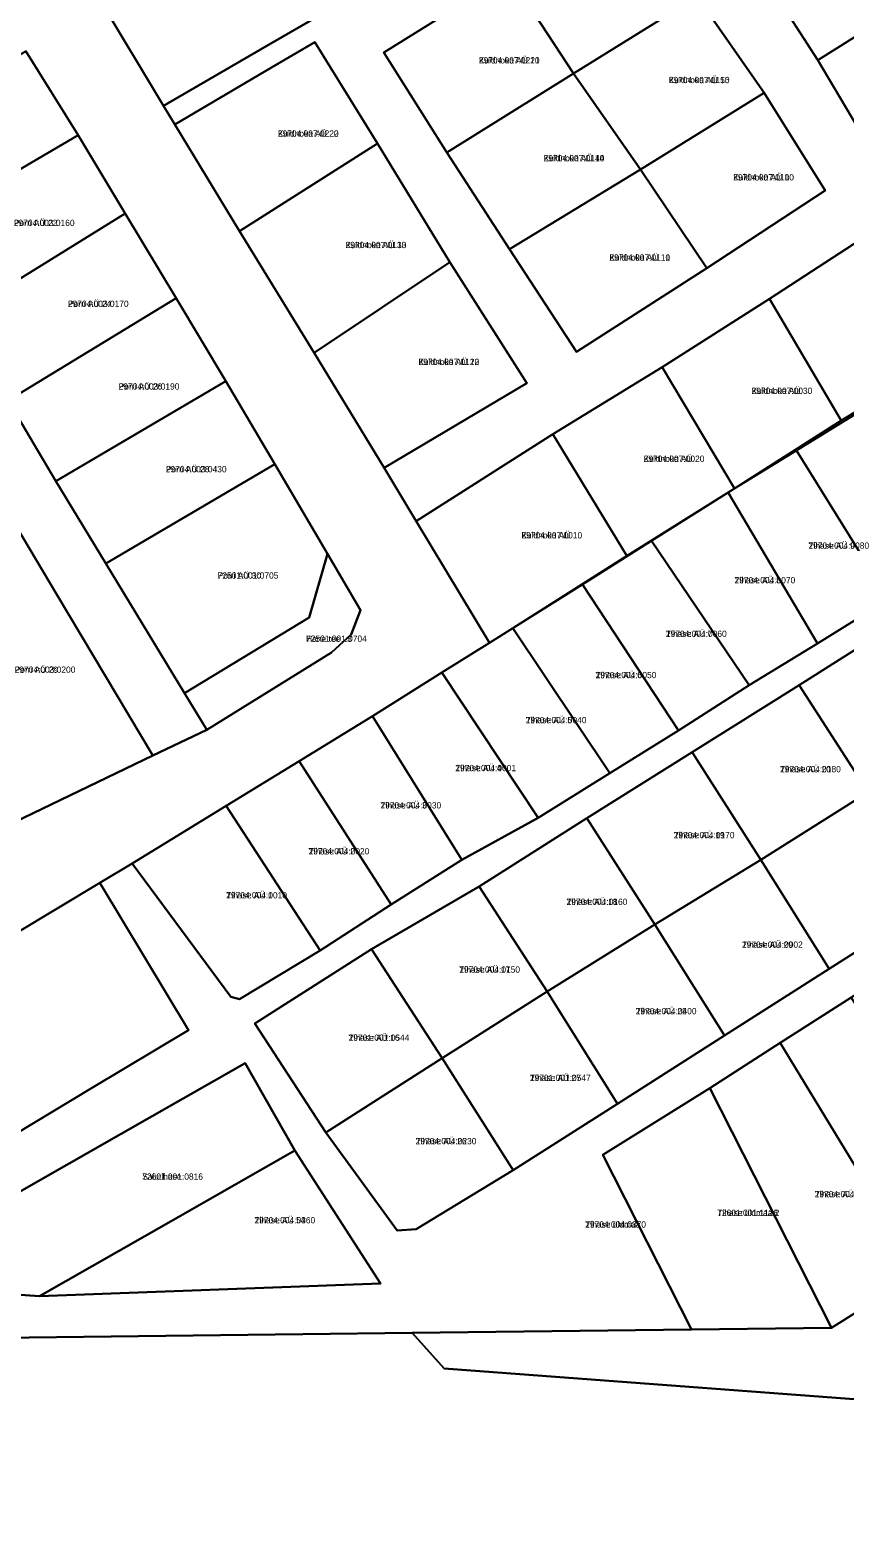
# Model space of a CAD drawing. Extents: x 504287 to 537970, y 6539941 to 6586214.
# Drawn here: x 516534.2 to 516728.7, y 6563396.7 to 6563756.4 of the extents above; entities that cross this region are included whole.
import ezdxf

# ---------------------------------------------------------------- set-up
doc = ezdxf.new("R2010")
doc.units = 0
for name, color, linetype in [('L_AADRESS', 7, 'Continuous'), ('PIIR', 7, 'Continuous'), ('TUNNUS', 7, 'Continuous')]:
    doc.layers.add(name, color=color, linetype=linetype)

msp = doc.modelspace()

# ---------------------------------------------------------------- linework, layer by layer
at = {"layer": 'PIIR'}
for points in [[(516722.29, 6563749.26), (516735.69, 6563726.63), (516766.07, 6563743.18), (516799.74, 6563764.29), (516785.62, 6563789.05), (516771.4, 6563813.09), (516757.06, 6563837.14), (516721.19, 6563815.1), (516692.06, 6563796.82), (516706.99, 6563772.95)], [(516623.67, 6563811.4), (516643.03, 6563783.07), (516624.17, 6563770.73), (516623.2, 6563772.02), (516617.83, 6563768.33), (516591.67, 6563753.24), (516566.1, 6563738.35), (516550.62, 6563764.18), (516575.1, 6563780.13), (516585.67, 6563787.07), (516593.53, 6563792.11), (516615.66, 6563806.42)], [(516706.99, 6563772.95), (516736.13, 6563791.14), (516751.12, 6563767.4), (516722.29, 6563749.26)], [(516648.67, 6563704.2), (516664.67, 6563679.71), (516695.76, 6563699.65), (516724.03, 6563718.14), (516709.44, 6563741.49), (516693.5, 6563764.43), (516679.56, 6563788.61), (516648.53, 6563769.72), (516618.65, 6563751.1), (516633.73, 6563727.26)], [(516648.53, 6563769.72), (516679.56, 6563788.61), (516693.5, 6563764.43), (516663.97, 6563746.07)], [(516618.65, 6563751.1), (516648.53, 6563769.72), (516663.97, 6563746.07), (516633.73, 6563727.26)], [(516663.97, 6563746.07), (516693.5, 6563764.43), (516709.44, 6563741.49), (516679.91, 6563723.16)], [(516722.29, 6563749.26), (516751.12, 6563767.4), (516766.07, 6563743.18), (516735.69, 6563726.63)], [(516568.78, 6563733.94), (516591.84, 6563747.49), (516602.18, 6563753.59), (516617.19, 6563729.39), (516584.22, 6563708.44)], [(516493.11, 6563727.7), (516533.21, 6563751.45), (516545.71, 6563731.34), (516505.34, 6563707.79)], [(516633.73, 6563727.26), (516663.97, 6563746.07), (516679.91, 6563723.16), (516648.67, 6563704.2)], [(516709.44, 6563741.49), (516724.03, 6563718.14), (516695.76, 6563699.65), (516679.91, 6563723.16)], [(516505.34, 6563707.79), (516545.71, 6563731.34), (516556.93, 6563712.69), (516517.08, 6563688.04)], [(516584.22, 6563708.44), (516617.19, 6563729.39), (516634.4, 6563701.07), (516602.05, 6563679.44)], [(516695.76, 6563699.65), (516664.67, 6563679.71), (516648.67, 6563704.2), (516679.91, 6563723.16)], [(516517.08, 6563688.04), (516556.93, 6563712.69), (516569.06, 6563692.51), (516528.99, 6563668.1)], [(516710.76, 6563692.3), (516732.39, 6563706.39), (516736.08, 6563707.1), (516752.91, 6563678.97), (516751.32, 6563677.47), (516727.82, 6563663.32)], [(516634.4, 6563701.07), (516652.8, 6563672.2), (516618.72, 6563651.98), (516602.05, 6563679.44)], [(516528.99, 6563668.1), (516569.06, 6563692.51), (516580.96, 6563672.68), (516540.37, 6563648.81)], [(516685.1, 6563676.01), (516710.76, 6563692.3), (516727.82, 6563663.32), (516702.36, 6563647.05)], [(516659.05, 6563660.05), (516685.1, 6563676.01), (516702.36, 6563647.05), (516676.66, 6563631)], [(516580.96, 6563672.68), (516592.61, 6563652.86), (516552.31, 6563629.16), (516540.37, 6563648.81)], [(516733.94, 6563666.48), (516756.7, 6563631.52), (516739.21, 6563620.66), (516717.18, 6563656.16)], [(516626.42, 6563639.26), (516659.05, 6563660.05), (516676.66, 6563631), (516649.46, 6563613.73), (516643.89, 6563610.25)], [(516702.36, 6563647.05), (516717.18, 6563656.16), (516739.21, 6563620.66), (516722.21, 6563610.11), (516700.84, 6563646.09)], [(516600.85, 6563616.31), (516571.09, 6563598.26), (516552.31, 6563629.16), (516592.61, 6563652.86), (516605.19, 6563631.46)], [(516700.84, 6563646.09), (516722.21, 6563610.11), (516705.92, 6563600.17), (516682.56, 6563634.57)], [(516497.49, 6563622.01), (516529.15, 6563640.98), (516540.67, 6563621.62), (516563.56, 6563583.34), (516530.47, 6563567.46), (516508.46, 6563602.44)], [(516682.56, 6563634.57), (516705.92, 6563600.17), (516688.99, 6563589.3), (516666.12, 6563624.14)], [(516605.19, 6563631.46), (516613.07, 6563618.05), (516610.84, 6563612.22), (516606.19, 6563607.91), (516576.41, 6563589.5), (516571.09, 6563598.26), (516600.85, 6563616.31)], [(516666.12, 6563624.14), (516688.99, 6563589.3), (516672.59, 6563579.17), (516649.46, 6563613.73)], [(516649.46, 6563613.73), (516672.59, 6563579.17), (516655.53, 6563568.5), (516632.5, 6563603.12), (516643.89, 6563610.25)], [(516743.18, 6563616.21), (516759.74, 6563590.32), (516759.36, 6563589.97), (516734.29, 6563574.56), (516717.81, 6563600.13)], [(516725.56, 6563446.76), (516746.61, 6563460.01), (516763.92, 6563471.26), (516781.08, 6563482.33), (516797.71, 6563493.29), (516814.71, 6563504.25), (516831.42, 6563515.11), (516848.12, 6563525.98), (516865.33, 6563536.97), (516882.68, 6563548.06), (516898.91, 6563558.38), (516921.33, 6563573.01), (516927.25, 6563577.2), (516982.09, 6563611.59), (517112.27, 6563384.86), (517064.02, 6563325.01), (516892.69, 6563483.77), (516884.06, 6563418.3), (516633.11, 6563437.06), (516625.46, 6563445.55), (516692.12, 6563446.36)], [(516632.5, 6563603.12), (516655.53, 6563568.5), (516637.29, 6563558.49), (516615.95, 6563592.72)], [(516692.25, 6563584.15), (516717.81, 6563600.13), (516734.29, 6563574.56), (516708.64, 6563558.48)], [(516615.95, 6563592.72), (516637.29, 6563558.49), (516620.44, 6563547.76), (516598.44, 6563581.96)], [(516598.44, 6563581.96), (516620.44, 6563547.76), (516603.46, 6563536.85), (516580.99, 6563571.31)], [(516667.15, 6563568.39), (516692.25, 6563584.15), (516708.64, 6563558.48), (516683.34, 6563543)], [(516734.29, 6563574.56), (516750.56, 6563548.68), (516725.02, 6563532.42), (516708.64, 6563558.48)], [(516580.99, 6563571.31), (516603.46, 6563536.85), (516584.18, 6563525.23), (516582.15, 6563525.76), (516558.61, 6563557.61)], [(516641.42, 6563552.09), (516667.15, 6563568.39), (516683.34, 6563543), (516657.65, 6563527.01)], [(516708.64, 6563558.48), (516725.02, 6563532.42), (516699.99, 6563516.5), (516683.34, 6563543)], [(516458.32, 6563497.36), (516550.89, 6563552.98), (516572.01, 6563517.83), (516548.86, 6563503.93), (516525.72, 6563490.03), (516502.57, 6563476.12), (516479.43, 6563462.22)], [(516641.42, 6563552.09), (516657.65, 6563527.01), (516632.63, 6563511.14), (516615.72, 6563537.12)], [(516683.34, 6563543), (516699.99, 6563516.5), (516674.46, 6563500.24), (516657.65, 6563527.01)], [(516615.72, 6563537.12), (516632.63, 6563511.14), (516604.84, 6563493.42), (516587.89, 6563519.38)], [(516657.65, 6563527.01), (516674.46, 6563500.24), (516649.55, 6563484.39), (516632.63, 6563511.14)], [(516730.23, 6563525.6), (516763.92, 6563471.26), (516746.61, 6563460.01), (516713.3, 6563514.8)], [(516713.3, 6563514.8), (516746.61, 6563460.01), (516725.56, 6563446.76), (516696.5, 6563504)], [(516617.86, 6563457.38), (516597.41, 6563489.08), (516585.53, 6563509.93), (516555.99, 6563493.09), (516493.29, 6563457.33), (516536.45, 6563454.32)], [(516493.29, 6563457.33), (516555.99, 6563493.09), (516585.53, 6563509.93), (516597.41, 6563489.08), (516567.88, 6563472.24), (516536.45, 6563454.32)], [(516649.55, 6563484.39), (516626.42, 6563470.34), (516621.82, 6563470.01), (516604.84, 6563493.42), (516632.63, 6563511.14)], [(516692.12, 6563446.36), (516670.97, 6563488.02), (516696.5, 6563504), (516725.56, 6563446.76)], [(516567.88, 6563472.24), (516597.41, 6563489.08), (516617.86, 6563457.38), (516536.45, 6563454.32)], [(516501.25, 6563444.05), (516625.46, 6563445.55), (516633.11, 6563437.06), (516884.06, 6563418.3), (516888.62, 6563294.88), (516865.54, 6563151.5), (516892.22, 6563104.11), (516896.52, 6563093.71), (516896.31, 6563070.84), (516900.68, 6563071.4), (516864.48, 6563024.66), (516715.46, 6563293.57), (516424.36, 6563426.81), (516408.82, 6563458.96)]]:
    msp.add_lwpolyline(points, close=True, dxfattribs=at)
for points in [[(516522.28, 6563810.4), (516536.31, 6563787.22), (516550.62, 6563764.18), (516566.1, 6563738.35), (516568.78, 6563733.94), (516584.22, 6563708.44), (516602.05, 6563679.44), (516618.72, 6563651.98), (516626.42, 6563639.26), (516643.89, 6563610.25), (516632.5, 6563603.12), (516615.95, 6563592.72), (516598.44, 6563581.96), (516580.99, 6563571.31), (516558.61, 6563557.61), (516550.89, 6563552.98), (516458.32, 6563497.36)], [(516814.57, 6563765.92), (516822.58, 6563752.44), (516835.52, 6563730.64), (516831.44, 6563728.29), (516813.56, 6563755.93), (516786.43, 6563739.01), (516761.12, 6563723.2), (516736.08, 6563707.11), (516732.39, 6563706.39), (516710.76, 6563692.3), (516685.1, 6563676.01), (516659.05, 6563660.05), (516626.42, 6563639.26), (516618.72, 6563651.98), (516652.8, 6563672.2), (516634.4, 6563701.07), (516617.19, 6563729.39), (516602.18, 6563753.59), (516591.84, 6563747.49), (516568.78, 6563733.94), (516566.1, 6563738.35), (516591.67, 6563753.24), (516617.83, 6563768.33)], [(516530.47, 6563567.46), (516563.56, 6563583.34), (516576.41, 6563589.5), (516606.19, 6563607.91), (516610.84, 6563612.22), (516613.07, 6563618.05), (516605.19, 6563631.46), (516592.61, 6563652.86), (516580.96, 6563672.68), (516569.06, 6563692.51), (516556.93, 6563712.69), (516545.71, 6563731.34), (516533.21, 6563751.45)], [(516528.99, 6563668.1), (516540.37, 6563648.81), (516552.31, 6563629.16), (516571.09, 6563598.26), (516576.41, 6563589.5), (516563.56, 6563583.34), (516540.67, 6563621.62), (516529.15, 6563640.98)], [(516921.33, 6563573.01), (516892.36, 6563626.23), (516866.43, 6563610.95), (516849.15, 6563600.15), (516831.7, 6563589.26), (516814.75, 6563578.77), (516797.92, 6563567.94), (516781.58, 6563557.53), (516764.15, 6563546.36), (516747.57, 6563536.38), (516730.23, 6563525.6), (516713.3, 6563514.8), (516696.5, 6563504), (516670.97, 6563488.02), (516692.12, 6563446.36), (516625.46, 6563445.55), (516501.25, 6563444.05)], [(516525.72, 6563490.03), (516548.86, 6563503.93), (516572.01, 6563517.83), (516550.89, 6563552.98), (516558.61, 6563557.61), (516582.15, 6563525.76), (516584.18, 6563525.23), (516603.46, 6563536.85), (516620.44, 6563547.76), (516637.29, 6563558.49), (516655.53, 6563568.5), (516672.59, 6563579.17), (516688.99, 6563589.3), (516705.92, 6563600.17), (516722.21, 6563610.11), (516739.21, 6563620.66)], [(516743.18, 6563616.21), (516717.81, 6563600.13), (516692.25, 6563584.15), (516667.15, 6563568.39), (516641.42, 6563552.09), (516615.72, 6563537.12), (516587.89, 6563519.38), (516604.84, 6563493.42), (516621.82, 6563470.01), (516626.42, 6563470.34), (516649.55, 6563484.39), (516674.46, 6563500.24), (516699.99, 6563516.5), (516725.02, 6563532.42), (516750.56, 6563548.68)]]:
    msp.add_lwpolyline(points, dxfattribs=at)

# ---------------------------------------------------------------- texts
at = {"layer": 'L_AADRESS'}
for s, p in [('Kuldnoka AÜ 21', (516641.35, 6563748.49)), ('Kuldnoka AÜ 15', (516686.7, 6563743.79)), ('Kuldnoka AÜ 22', (516593.37, 6563731.02)), ('Kuldnoka AÜ 14', (516656.82, 6563725.13)), ('Kuldnoka AÜ 10', (516702.08, 6563720.57)), ('Porri AÜ 22', (516530.34, 6563709.69)), ('Kuldnoka AÜ 13', (516609.53, 6563704.42)), ('Kuldnoka AÜ 11', (516672.52, 6563701.44)), ('Porri AÜ 24', (516543.24, 6563690.4)), ('Kuldnoka AÜ 12', (516626.93, 6563676.53)), ('Porri AÜ 26', (516555.36, 6563670.66)), ('Kuldnoka AÜ 3', (516706.46, 6563669.62)), ('Porri AÜ 28', (516566.63, 6563650.92)), ('Kuldnoka AÜ 2', (516680.7, 6563653.42)), ('Kuldnoka AÜ 1', (516651.52, 6563635.15)), ('Tihase AÜ 9', (516720.03, 6563632.68)), ('Porri AÜ 30', (516579, 6563625.56)), ('Tihase AÜ 8', (516702.39, 6563624.43)), ('Tihase AÜ 7', (516686.02, 6563611.65)), ('Hane tee L3', (516600.1, 6563610.48)), ('Porri AÜ 29', (516530.53, 6563603.08)), ('Tihase AÜ 6', (516669.23, 6563601.8)), ('Tihase AÜ 5', (516652.55, 6563591.05)), ('Tihase AÜ 4', (516635.74, 6563579.61)), ('Tihase AÜ 20', (516713.27, 6563579.34)), ('Tihase AÜ 3', (516617.86, 6563570.71)), ('Tihase AÜ 19', (516687.89, 6563563.6)), ('Tihase AÜ 2', (516600.71, 6563559.74)), ('Tihase AÜ 1', (516581.04, 6563549.25)), ('Tihase AÜ 18', (516662.3, 6563547.7)), ('Tihase AÜ 29', (516704.18, 6563537.46)), ('Tihase AÜ 17', (516636.68, 6563531.52)), ('Tihase AÜ 28', (516678.82, 6563521.6)), ('Tihase AÜ 16', (516610.26, 6563515.27)), ('Tihase AÜ 27', (516653.55, 6563505.67)), ('Tihase AÜ 26', (516626.27, 6563490.58)), ('Salutihase', (516560.99, 6563482.12)), ('Tihase AÜ 36', (516721.55, 6563477.94)), ('Tihase AÜ 54', (516587.78, 6563471.7)), ('Tihase üldmaa 2', (516698.27, 6563473.48)), ('Tihase üldmaa', (516666.75, 6563470.69))]:
    msp.add_text(s, height=1.5, dxfattribs=at).set_placement(p)
at = {"layer": 'TUNNUS'}
for s, p in [('29704:007:0210', (516641.35, 6563748.49)), ('29704:007:0150', (516686.7, 6563743.79)), ('29704:007:0220', (516593.37, 6563731.02)), ('29704:007:0140', (516656.82, 6563725.13)), ('29704:007:0100', (516702.08, 6563720.57)), ('29704:003:0160', (516530.34, 6563709.69)), ('29704:007:0130', (516609.53, 6563704.42)), ('29704:007:0110', (516672.52, 6563701.44)), ('29704:003:0170', (516543.24, 6563690.4)), ('29704:007:0120', (516626.93, 6563676.53)), ('29704:003:0190', (516555.36, 6563670.66)), ('29704:007:0030', (516706.46, 6563669.62)), ('29704:007:0020', (516680.7, 6563653.42)), ('29704:003:0430', (516566.63, 6563650.92)), ('29704:007:0010', (516651.52, 6563635.15)), ('29704:004:0080', (516720.03, 6563632.68)), ('72501:001:0705', (516579, 6563625.56)), ('29704:004:0070', (516702.39, 6563624.43)), ('29704:004:0060', (516686.02, 6563611.65)), ('72501:001:0704', (516600.1, 6563610.48)), ('29704:003:0200', (516530.53, 6563603.08)), ('29704:004:0050', (516669.23, 6563601.8)), ('29704:004:0040', (516652.55, 6563591.05)), ('29704:004:0001', (516635.74, 6563579.61)), ('29704:004:0180', (516713.27, 6563579.34)), ('29704:004:0030', (516617.86, 6563570.71)), ('29704:004:0170', (516687.89, 6563563.6)), ('29704:004:0020', (516600.71, 6563559.74)), ('29704:004:0010', (516581.04, 6563549.25)), ('29704:004:0160', (516662.3, 6563547.7)), ('29704:004:0002', (516704.18, 6563537.46)), ('29704:004:0150', (516636.68, 6563531.52)), ('29704:004:0400', (516678.82, 6563521.6)), ('29701:001:0544', (516610.26, 6563515.27)), ('29701:001:0547', (516653.55, 6563505.67)), ('29704:004:0230', (516626.27, 6563490.58)), ('72601:001:0816', (516560.99, 6563482.12)), ('29704:004:0420', (516721.55, 6563477.94)), ('29704:004:0360', (516587.78, 6563471.7)), ('72601:001:1128', (516698.27, 6563473.48)), ('29704:004:0370', (516666.75, 6563470.69))]:
    msp.add_text(s, height=1.5, dxfattribs=at).set_placement(p)

doc.saveas('drawing.dxf')
